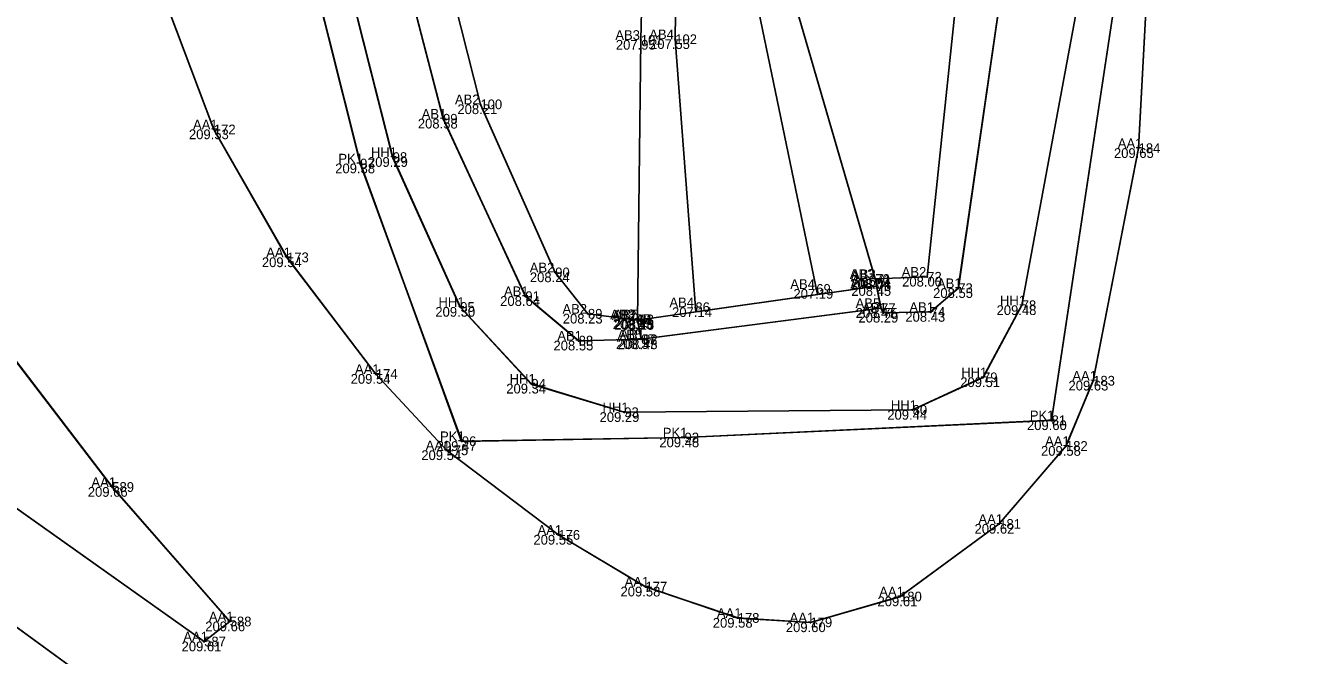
# Model space of a CAD drawing. Extents: x -263091 to -262565, y -1238731 to -1237092.
# Drawn here: x -262957.98 to -262931.8, y -1238394.45 to -1238381.51 of the extents above; entities that cross this region are included whole.
import ezdxf

# ---------------------------------------------------------------- set-up
doc = ezdxf.new("R2010")
doc.units = 0
for name, color, linetype in [('01_Hrana_betónu', 7, 'Continuous'), ('02_Oplotenie', 7, 'Continuous'), ('03_Asfalt', 7, 'Continuous'), ('05_Hrana_terénu', 7, 'Continuous'), ('07_Iné', 7, 'Continuous'), ('10', 7, 'Continuous'), ('Groma (21)', 7, 'Continuous'), ('Groma (22)', 7, 'Continuous'), ('Groma (23)', 7, 'Continuous'), ('Groma (24)', 7, 'Continuous'), ('U001_Zeleň_mimo', 7, 'Continuous'), ('U002_Asfalt', 7, 'Continuous'), ('U002_Betónové panely', 7, 'Continuous'), ('U002_Betóny_prídavné', 7, 'Continuous'), ('U002_Zeleň_mimo', 7, 'Continuous'), ('U002_Zeleň_vnútro', 7, 'Continuous'), ('U002_Zeleň_zatrávňovač', 7, 'Continuous')]:
    doc.layers.add(name, color=color, linetype=linetype)

msp = doc.modelspace()

# ---------------------------------------------------------------- linework, layer by layer
at = {"layer": '01_Hrana_betónu'}
for points in [[(-262944.213, -1238387.387), (-262944.634, -1238381.789), (-262944.5, -1238371.343), (-262941.2, -1238360.927), (-262935.086, -1238341.218), (-262927.632, -1238317.179), (-262920.793, -1238295.265), (-262911.171, -1238262.813), (-262915.352, -1238261.064), (-262915.337, -1238259.329), (-262909.866, -1238261.629), (-262904.904, -1238263.716)], [(-262916.095, -1238261.519), (-262911.974, -1238263.293), (-262921.591, -1238294.909), (-262928.534, -1238317.073), (-262935.896, -1238340.99), (-262941.971, -1238360.685), (-262945.096, -1238371.115), (-262945.34, -1238381.803), (-262945.412, -1238387.557)], [(-262941.714, -1238387.032), (-262942.991, -1238380.859), (-262943.934, -1238373.35), (-262940.485, -1238361.041), (-262934.456, -1238341.421), (-262927.277, -1238318.134), (-262920.116, -1238294.802), (-262913.64, -1238273.614), (-262910.214, -1238263.245), (-262905.769, -1238265.099), (-262904.904, -1238263.716)], [(-262905.769, -1238265.099), (-262909.81, -1238264.181), (-262912.956, -1238273.861), (-262919.396, -1238295.066), (-262926.538, -1238318.409), (-262933.693, -1238341.579), (-262939.683, -1238361.151), (-262943.246, -1238373.477), (-262942.259, -1238380.752), (-262940.526, -1238386.713)], [(-262905.769, -1238265.099), (-262909.014, -1238275.12), (-262915.393, -1238296.189), (-262922.597, -1238319.497), (-262929.796, -1238342.936), (-262935.083, -1238362.17), (-262937.995, -1238374.567), (-262938.788, -1238380.26), (-262939.46, -1238386.668), (-262940.526, -1238386.713), (-262940.498, -1238386.859)], [(-262940.36, -1238387.407), (-262939.388, -1238387.391), (-262938.822, -1238386.902), (-262937.88, -1238380.385), (-262937.119, -1238374.802), (-262934.23, -1238362.39), (-262928.952, -1238343.2), (-262921.717, -1238319.813), (-262915.107, -1238298.192), (-262908.208, -1238275.423), (-262904.855, -1238265.436)], [(-262945.333, -1238387.95), (-262946.617, -1238387.98), (-262947.712, -1238387.066), (-262949.402, -1238383.422), (-262952.187, -1238372.656), (-262952.759, -1238366.382)], [(-262951.91, -1238366.581), (-262951.321, -1238372.499), (-262948.634, -1238383.126), (-262947.098, -1238386.578), (-262946.426, -1238387.428), (-262945.412, -1238387.557)], [(-262945.333, -1238387.95), (-262945.412, -1238387.557), (-262944.213, -1238387.387), (-262941.714, -1238387.032), (-262940.498, -1238386.859), (-262940.407, -1238387.311), (-262940.36, -1238387.407)]]:
    msp.add_lwpolyline(points, dxfattribs=at)
at = {"layer": '02_Oplotenie'}
msp.add_lwpolyline([(-262939.39, -1238320.83), (-262941.19, -1238324.79), (-262946.68, -1238336.9), (-262951.035, -1238350.68), (-262953.195, -1238358.97), (-262953.815, -1238358.809), (-262955.312, -1238364.513), (-262954.553, -1238364.724), (-262954.681, -1238366.785), (-262954.024, -1238372.698), (-262951.104, -1238384.342), (-262949.016, -1238390.045), (-262944.443, -1238389.969), (-262936.906, -1238389.616), (-262935.581, -1238380.82), (-262934.566, -1238375.513), (-262931.812, -1238363.194), (-262926.159, -1238344.076), (-262918.903, -1238320.384), (-262912.242, -1238298.942), (-262905.326, -1238276.054), (-262902.598, -1238266.292), (-262902.107, -1238264.892)], dxfattribs=at)
at = {"layer": '03_Asfalt'}
for points in [[(-262931.199, -1238364.162), (-262933.003, -1238372.216), (-262934.974, -1238381.221), (-262935.119, -1238384.027), (-262936.052, -1238388.803), (-262936.611, -1238390.144), (-262937.981, -1238391.744), (-262940.017, -1238393.235), (-262941.857, -1238393.766), (-262943.351, -1238393.675), (-262945.246, -1238393.033), (-262947.034, -1238391.969), (-262949.331, -1238390.232), (-262950.782, -1238388.665), (-262952.605, -1238386.269), (-262954.108, -1238383.642), (-262955.193, -1238380.77), (-262956.307, -1238376.99), (-262956.874, -1238372.978), (-262956.554, -1238367.788), (-262955.999, -1238364.917)], [(-262967.893, -1238384.386), (-262961.125, -1238389.323), (-262954.307, -1238394.16), (-262953.782, -1238393.748), (-262956.194, -1238390.986), (-262959.165, -1238387.112), (-262961.145, -1238384.138), (-262962.629, -1238381.652), (-262966.72, -1238383.885)], [(-262954.673, -1238396.412), (-262962.054, -1238391.026), (-262968.907, -1238386.238), (-262974.83, -1238389.493)]]:
    msp.add_lwpolyline(points, dxfattribs=at)
at = {"layer": '05_Hrana_terénu'}
msp.add_lwpolyline([(-262920.126, -1238320.151), (-262927.385, -1238343.686), (-262932.704, -1238362.854), (-262935.453, -1238375.219), (-262936.279, -1238380.57), (-262937.519, -1238387.253), (-262938.314, -1238388.733), (-262939.759, -1238389.403), (-262945.681, -1238389.45), (-262947.587, -1238388.865), (-262949.049, -1238387.288), (-262950.436, -1238384.21), (-262953.347, -1238372.702), (-262953.777, -1238366.63), (-262954.163, -1238366.041), (-262952.487, -1238358.01), (-262951.855, -1238357.25), (-262949.897, -1238349.853), (-262950.29, -1238348.92), (-262949.45, -1238345.83), (-262948.76, -1238345.496), (-262946.63, -1238339.15), (-262945.04, -1238334.12), (-262941.75, -1238326.63)], dxfattribs=at)
at = {"layer": '07_Iné'}
msp.add_lwpolyline([(-262940.407, -1238387.311), (-262940.498, -1238386.859), (-262945.412, -1238387.557), (-262945.334, -1238387.946)], close=True, dxfattribs=at)
at = {"layer": '10'}
msp.add_lwpolyline([(-262982.434, -1238375.977), (-262968.907, -1238386.238), (-262962.054, -1238391.026), (-262954.673, -1238396.412), (-262941.774, -1238405.784), (-262928.896, -1238415.327), (-262917.716, -1238423.993), (-262905.824, -1238433.621), (-262895.067, -1238441.663), (-262870.407, -1238460.6)], dxfattribs=at)
at = {"layer": 'Groma (21)'}
for centre in [(-262945.34, -1238381.803), (-262944.634, -1238381.789), (-262948.634, -1238383.126), (-262954.108, -1238383.642), (-262949.402, -1238383.422), (-262935.119, -1238384.027), (-262951.104, -1238384.342), (-262950.436, -1238384.21), (-262952.605, -1238386.269), (-262947.098, -1238386.578), (-262940.526, -1238386.713), (-262940.499, -1238386.717), (-262939.46, -1238386.668), (-262941.738, -1238386.918), (-262940.498, -1238386.859), (-262938.822, -1238386.902), (-262949.049, -1238387.288), (-262947.712, -1238387.066), (-262944.22, -1238387.294), (-262940.407, -1238387.311), (-262937.519, -1238387.253), (-262946.426, -1238387.428), (-262945.444, -1238387.54), (-262945.412, -1238387.557), (-262945.37, -1238387.544), (-262940.36, -1238387.407), (-262939.388, -1238387.391), (-262946.617, -1238387.98), (-262945.333, -1238387.95), (-262945.294, -1238387.955), (-262950.782, -1238388.665), (-262947.587, -1238388.865), (-262938.314, -1238388.733), (-262936.052, -1238388.803), (-262939.759, -1238389.403), (-262945.681, -1238389.45), (-262936.906, -1238389.616), (-262949.016, -1238390.045), (-262944.443, -1238389.969), (-262936.611, -1238390.144), (-262949.331, -1238390.232), (-262956.194, -1238390.986), (-262937.981, -1238391.744), (-262947.034, -1238391.969), (-262945.246, -1238393.033), (-262940.017, -1238393.235), (-262953.782, -1238393.748), (-262943.351, -1238393.675), (-262941.857, -1238393.766), (-262954.307, -1238394.16)]:
    msp.add_circle(centre, 0.01, dxfattribs=at)
at = {"layer": 'U001_Zeleň_mimo'}
msp.add_lwpolyline([(-262966.43, -1238405.69), (-262974.83, -1238389.49), (-262968.91, -1238386.24), (-262962.05, -1238391.03), (-262954.67, -1238396.41)], dxfattribs=at)
at = {"layer": 'U002_Asfalt'}
for points in [[(-262962.63, -1238381.65), (-262956.31, -1238376.99), (-262955.19, -1238380.77), (-262954.11, -1238383.64), (-262952.61, -1238386.27), (-262950.78, -1238388.67), (-262949.33, -1238390.23), (-262947.03, -1238391.97), (-262945.25, -1238393.03), (-262943.35, -1238393.68), (-262941.86, -1238393.77), (-262940.02, -1238393.24), (-262937.98, -1238391.74), (-262936.61, -1238390.14), (-262936.05, -1238388.8), (-262935.12, -1238384.03), (-262934.97, -1238381.22), (-262933, -1238372.22), (-262931.2, -1238364.16)], [(-262962.63, -1238381.65), (-262956.31, -1238376.99), (-262955.19, -1238380.77), (-262954.11, -1238383.64), (-262952.61, -1238386.27), (-262950.78, -1238388.67), (-262949.33, -1238390.23), (-262947.03, -1238391.97), (-262945.25, -1238393.03), (-262943.35, -1238393.68), (-262941.86, -1238393.77), (-262940.02, -1238393.24), (-262937.98, -1238391.74), (-262936.61, -1238390.14), (-262936.05, -1238388.8), (-262935.12, -1238384.03), (-262934.97, -1238381.22), (-262933, -1238372.22), (-262931.2, -1238364.16)], [(-262961.13, -1238389.32), (-262954.31, -1238394.16), (-262953.78, -1238393.75), (-262956.19, -1238390.99), (-262959.16, -1238387.11)], [(-262961.13, -1238389.32), (-262954.31, -1238394.16), (-262953.78, -1238393.75), (-262956.19, -1238390.99), (-262959.16, -1238387.11)], [(-262954.67, -1238396.41), (-262962.05, -1238391.03)], [(-262954.67, -1238396.41), (-262962.05, -1238391.03)]]:
    msp.add_lwpolyline(points, dxfattribs=at)
at = {"layer": 'U002_Betónové panely'}
msp.add_lwpolyline([(-262934.23, -1238362.39), (-262937.12, -1238374.8), (-262937.88, -1238380.39), (-262938.82, -1238386.9), (-262939.39, -1238387.39), (-262940.36, -1238387.41), (-262940.41, -1238387.31), (-262940.5, -1238386.86), (-262941.71, -1238387.03), (-262944.21, -1238387.39), (-262945.41, -1238387.56), (-262945.33, -1238387.95), (-262946.62, -1238387.98), (-262947.71, -1238387.07), (-262949.4, -1238383.42), (-262952.19, -1238372.66), (-262952.76, -1238366.38)], dxfattribs=at)
msp.add_lwpolyline([(-262934.23, -1238362.39), (-262937.12, -1238374.8), (-262937.88, -1238380.39), (-262938.82, -1238386.9), (-262939.39, -1238387.39), (-262940.36, -1238387.41), (-262940.41, -1238387.31), (-262940.5, -1238386.86), (-262941.71, -1238387.03), (-262944.21, -1238387.39), (-262945.41, -1238387.56), (-262945.33, -1238387.95), (-262946.62, -1238387.98), (-262947.71, -1238387.07), (-262949.4, -1238383.42), (-262952.19, -1238372.66), (-262952.76, -1238366.38)], dxfattribs=at)
at = {"layer": 'U002_Betóny_prídavné'}
msp.add_lwpolyline([(-262940.5, -1238386.86), (-262940.41, -1238387.31), (-262945.33, -1238387.95), (-262945.41, -1238387.56)], close=True, dxfattribs=at)
at = {"layer": 'U002_Zeleň_mimo'}
for points in [[(-262954.68, -1238366.78), (-262954.02, -1238372.7), (-262951.1, -1238384.34), (-262949.02, -1238390.05), (-262944.44, -1238389.97), (-262936.91, -1238389.62), (-262935.58, -1238380.82), (-262934.57, -1238375.51), (-262931.81, -1238363.19)], [(-262931.2, -1238364.16), (-262933, -1238372.22), (-262934.97, -1238381.22), (-262935.12, -1238384.03), (-262936.05, -1238388.8), (-262936.61, -1238390.14), (-262937.98, -1238391.74), (-262940.02, -1238393.24), (-262941.86, -1238393.77), (-262943.35, -1238393.68), (-262945.25, -1238393.03), (-262947.03, -1238391.97), (-262949.33, -1238390.23), (-262950.78, -1238388.67), (-262952.61, -1238386.27), (-262954.11, -1238383.64), (-262955.19, -1238380.77), (-262956.31, -1238376.99), (-262956.87, -1238372.98), (-262956.55, -1238367.79), (-262956, -1238364.92)]]:
    msp.add_lwpolyline(points, dxfattribs=at)
msp.add_lwpolyline([(-262961.15, -1238384.14), (-262959.16, -1238387.11), (-262956.19, -1238390.99), (-262953.78, -1238393.75), (-262954.31, -1238394.16), (-262961.13, -1238389.32), (-262967.89, -1238384.39), (-262966.72, -1238383.89), (-262962.63, -1238381.65)], close=True, dxfattribs=at)
at = {"layer": 'U002_Zeleň_vnútro'}
for points in [[(-262918.9, -1238320.38), (-262926.16, -1238344.08), (-262931.81, -1238363.19), (-262934.57, -1238375.51), (-262935.58, -1238380.82), (-262936.91, -1238389.62), (-262944.44, -1238389.97), (-262949.02, -1238390.05), (-262951.1, -1238384.34), (-262954.02, -1238372.7), (-262954.68, -1238366.78), (-262954.55, -1238364.72), (-262955.31, -1238364.51), (-262953.82, -1238358.81), (-262953.2, -1238358.97), (-262951.03, -1238350.68), (-262946.68, -1238336.9), (-262941.19, -1238324.79)], [(-262918.9, -1238320.38), (-262926.16, -1238344.08), (-262931.81, -1238363.19), (-262934.57, -1238375.51), (-262935.58, -1238380.82), (-262936.91, -1238389.62), (-262944.44, -1238389.97), (-262949.02, -1238390.05)], [(-262949.02, -1238390.05), (-262951.1, -1238384.34), (-262954.02, -1238372.7), (-262954.68, -1238366.78), (-262954.55, -1238364.72), (-262955.31, -1238364.51), (-262953.82, -1238358.81), (-262953.2, -1238358.97), (-262951.03, -1238350.68), (-262946.68, -1238336.9), (-262941.19, -1238324.79)], [(-262953.78, -1238366.63), (-262953.35, -1238372.7), (-262950.44, -1238384.21), (-262949.05, -1238387.29), (-262947.59, -1238388.87), (-262945.68, -1238389.45), (-262939.76, -1238389.4), (-262938.31, -1238388.73), (-262937.52, -1238387.25), (-262936.28, -1238380.57), (-262935.45, -1238375.22), (-262932.7, -1238362.85)], [(-262953.78, -1238366.63), (-262953.35, -1238372.7), (-262950.44, -1238384.21), (-262949.05, -1238387.29), (-262947.59, -1238388.87), (-262945.68, -1238389.45), (-262939.76, -1238389.4), (-262938.31, -1238388.73), (-262937.52, -1238387.25), (-262936.28, -1238380.57), (-262935.45, -1238375.22), (-262932.7, -1238362.85)]]:
    msp.add_lwpolyline(points, dxfattribs=at)
at = {"layer": 'U002_Zeleň_zatrávňovač'}
for points in [[(-262945.68, -1238389.45), (-262947.59, -1238388.87), (-262949.05, -1238387.29), (-262950.44, -1238384.21), (-262953.35, -1238372.7), (-262953.78, -1238366.63), (-262954.16, -1238366.04), (-262952.76, -1238366.38), (-262952.19, -1238372.66), (-262949.4, -1238383.42), (-262947.71, -1238387.07), (-262946.62, -1238387.98), (-262945.33, -1238387.95), (-262940.41, -1238387.31), (-262940.36, -1238387.41), (-262939.39, -1238387.39), (-262938.82, -1238386.9), (-262937.88, -1238380.39), (-262937.12, -1238374.8), (-262934.23, -1238362.39), (-262928.95, -1238343.2), (-262921.72, -1238319.81)], [(-262920.13, -1238320.15), (-262927.39, -1238343.69), (-262932.7, -1238362.85), (-262935.45, -1238375.22), (-262936.28, -1238380.57), (-262937.52, -1238387.25), (-262938.31, -1238388.73), (-262939.76, -1238389.4), (-262945.68, -1238389.45)], [(-262952.76, -1238366.38), (-262952.19, -1238372.66), (-262949.4, -1238383.42), (-262947.71, -1238387.07), (-262946.62, -1238387.98), (-262945.33, -1238387.95), (-262940.41, -1238387.31), (-262940.36, -1238387.41), (-262939.39, -1238387.39), (-262938.82, -1238386.9), (-262937.88, -1238380.39), (-262937.12, -1238374.8), (-262934.23, -1238362.39)], [(-262932.7, -1238362.85), (-262935.45, -1238375.22), (-262936.28, -1238380.57), (-262937.52, -1238387.25), (-262938.31, -1238388.73), (-262939.76, -1238389.4), (-262945.68, -1238389.45), (-262947.59, -1238388.87), (-262949.05, -1238387.29), (-262950.44, -1238384.21), (-262953.35, -1238372.7), (-262953.78, -1238366.63)]]:
    msp.add_lwpolyline(points, dxfattribs=at)

# ---------------------------------------------------------------- texts
at = {"layer": 'Groma (22)'}
for s, p in [('101', (-262945.34, -1238381.903)), ('102', (-262944.634, -1238381.889)), ('100', (-262948.634, -1238383.226)), ('99', (-262949.402, -1238383.522)), ('172', (-262954.108, -1238383.742)), ('98', (-262950.436, -1238384.31)), ('184', (-262935.119, -1238384.127)), ('97', (-262951.104, -1238384.442)), ('173', (-262952.605, -1238386.369)), ('90', (-262947.098, -1238386.678)), ('70', (-262940.526, -1238386.813)), ('71', (-262940.499, -1238386.817)), ('76', (-262940.498, -1238386.959)), ('72', (-262939.46, -1238386.768)), ('91', (-262947.712, -1238387.166)), ('69', (-262941.738, -1238387.018)), ('73', (-262938.822, -1238387.002)), ('95', (-262949.049, -1238387.388)), ('86', (-262944.22, -1238387.394)), ('77', (-262940.407, -1238387.411)), ('75', (-262940.36, -1238387.507)), ('74', (-262939.388, -1238387.491)), ('78', (-262937.519, -1238387.353)), ('89', (-262946.426, -1238387.528)), ('85', (-262945.444, -1238387.64)), ('84', (-262945.412, -1238387.657)), ('83', (-262945.37, -1238387.644)), ('88', (-262946.617, -1238388.08)), ('87', (-262945.333, -1238388.05)), ('82', (-262945.294, -1238388.055)), ('174', (-262950.782, -1238388.765)), ('94', (-262947.587, -1238388.965)), ('79', (-262938.314, -1238388.833)), ('183', (-262936.052, -1238388.903)), ('93', (-262945.681, -1238389.55)), ('80', (-262939.759, -1238389.503)), ('81', (-262936.906, -1238389.716)), ('92', (-262944.443, -1238390.069)), ('175', (-262949.331, -1238390.332)), ('96', (-262949.016, -1238390.145)), ('182', (-262936.611, -1238390.244)), ('589', (-262956.194, -1238391.086)), ('181', (-262937.981, -1238391.844)), ('176', (-262947.034, -1238392.069)), ('177', (-262945.246, -1238393.133)), ('180', (-262940.017, -1238393.335)), ('178', (-262943.351, -1238393.775)), ('588', (-262953.782, -1238393.848)), ('179', (-262941.857, -1238393.866)), ('587', (-262954.307, -1238394.26))]:
    msp.add_text(s, height=0.2, dxfattribs=at).set_placement(p)
at = {"layer": 'Groma (23)'}
for s, p in [('207.95', (-262945.853, -1238382.003)), ('207.55', (-262945.151, -1238381.989)), ('208.21', (-262949.107, -1238383.326)), ('209.53', (-262954.62, -1238383.842)), ('208.58', (-262949.919, -1238383.622)), ('209.65', (-262935.626, -1238384.227)), ('209.38', (-262951.616, -1238384.542)), ('209.29', (-262950.943, -1238384.41)), ('209.54', (-262953.122, -1238386.469)), ('208.24', (-262947.619, -1238386.778)), ('208.04', (-262941.046, -1238386.913)), ('208.04', (-262941.019, -1238386.917)), ('208.00', (-262939.975, -1238386.868)), ('207.19', (-262942.207, -1238387.118)), ('208.45', (-262941.019, -1238387.059)), ('208.55', (-262939.339, -1238387.102)), ('209.30', (-262949.56, -1238387.488)), ('208.64', (-262948.229, -1238387.266)), ('207.14', (-262944.699, -1238387.494)), ('208.47', (-262940.929, -1238387.511)), ('209.48', (-262938.036, -1238387.453)), ('208.23', (-262946.943, -1238387.628)), ('208.13', (-262945.917, -1238387.74)), ('208.40', (-262945.89, -1238387.744)), ('208.15', (-262945.885, -1238387.757)), ('208.29', (-262940.872, -1238387.607)), ('208.43', (-262939.909, -1238387.591)), ('208.55', (-262947.134, -1238388.18)), ('208.37', (-262945.85, -1238388.15)), ('208.43', (-262945.815, -1238388.155)), ('209.54', (-262951.299, -1238388.865)), ('209.34', (-262948.104, -1238389.065)), ('209.51', (-262938.782, -1238388.933)), ('209.63', (-262936.559, -1238389.003)), ('209.44', (-262940.28, -1238389.603)), ('209.29', (-262946.188, -1238389.65)), ('209.60', (-262937.412, -1238389.816)), ('209.47', (-262949.533, -1238390.245)), ('209.48', (-262944.96, -1238390.169)), ('209.58', (-262937.123, -1238390.344)), ('209.54', (-262949.848, -1238390.432)), ('209.66', (-262956.696, -1238391.186)), ('209.62', (-262938.488, -1238391.944)), ('209.55', (-262947.546, -1238392.169)), ('209.58', (-262945.758, -1238393.233)), ('209.61', (-262940.481, -1238393.435)), ('209.66', (-262954.284, -1238393.948)), ('209.58', (-262943.863, -1238393.875)), ('209.60', (-262942.363, -1238393.966)), ('209.61', (-262954.771, -1238394.36))]:
    msp.add_text(s, height=0.2, dxfattribs=at).set_placement(p)
at = {"layer": 'Groma (24)'}
for s, p in [('AB3', (-262945.864, -1238381.803)), ('AB4', (-262945.168, -1238381.789)), ('AB2', (-262949.158, -1238383.126)), ('AB1', (-262949.84, -1238383.422)), ('AA1', (-262954.536, -1238383.642)), ('AA1', (-262935.547, -1238384.027)), ('PK1', (-262951.551, -1238384.342)), ('HH1', (-262950.883, -1238384.21)), ('AA1', (-262953.033, -1238386.269)), ('AB2', (-262947.622, -1238386.578)), ('AB3', (-262941.05, -1238386.713)), ('AB2', (-262941.023, -1238386.717)), ('AB2', (-262939.984, -1238386.668)), ('AB4', (-262942.272, -1238386.918)), ('AB5', (-262941.022, -1238386.859)), ('AB1', (-262939.26, -1238386.902)), ('AB1', (-262948.15, -1238387.066)), ('HH1', (-262949.496, -1238387.288)), ('AB2', (-262946.95, -1238387.428)), ('AB4', (-262944.754, -1238387.294)), ('AB5', (-262940.931, -1238387.311)), ('AB1', (-262940.798, -1238387.407)), ('AB1', (-262939.826, -1238387.391)), ('HH1', (-262937.966, -1238387.253)), ('AB3', (-262945.968, -1238387.54)), ('AB2', (-262945.936, -1238387.557)), ('AB5', (-262945.894, -1238387.544)), ('AB1', (-262947.055, -1238387.98)), ('AB5', (-262945.818, -1238387.955)), ('AB1', (-262945.771, -1238387.95)), ('AA1', (-262951.21, -1238388.665)), ('HH1', (-262938.761, -1238388.733)), ('AA1', (-262936.48, -1238388.803)), ('HH1', (-262948.034, -1238388.865)), ('HH1', (-262946.128, -1238389.45)), ('HH1', (-262940.206, -1238389.403)), ('PK1', (-262937.353, -1238389.616)), ('PK1', (-262949.463, -1238390.045)), ('PK1', (-262944.89, -1238389.969)), ('AA1', (-262949.759, -1238390.232)), ('AA1', (-262937.039, -1238390.144)), ('AA1', (-262956.622, -1238390.986)), ('AA1', (-262938.409, -1238391.744)), ('AA1', (-262947.462, -1238391.969)), ('AA1', (-262945.674, -1238393.033)), ('AA1', (-262940.445, -1238393.235)), ('AA1', (-262954.21, -1238393.748)), ('AA1', (-262943.779, -1238393.675)), ('AA1', (-262942.285, -1238393.766)), ('AA1', (-262954.735, -1238394.16))]:
    msp.add_text(s, height=0.2, dxfattribs=at).set_placement(p)

doc.saveas('drawing.dxf')
